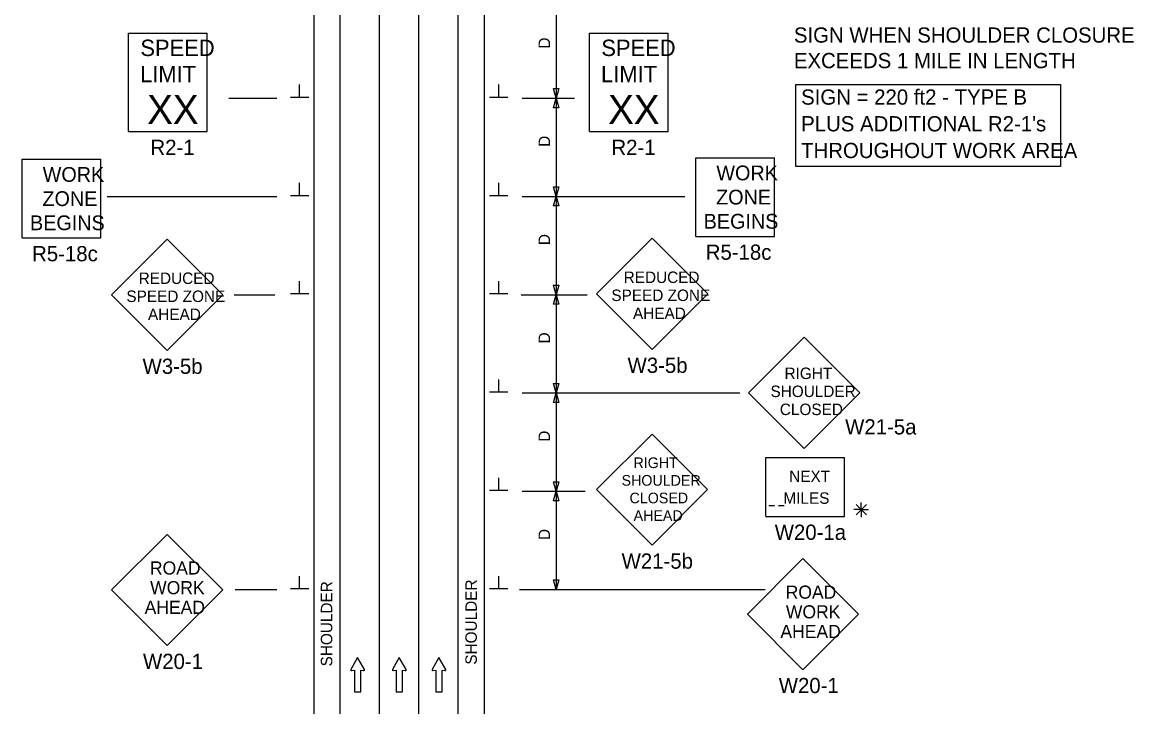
# Model space of a CAD drawing. Extents: x 16733 to 18471, y 7027 to 8225.
# Drawn here: x 16768 to 17446, y 7435 to 7852 of the extents above; entities that cross this region are included whole.
import ezdxf

# ---------------------------------------------------------------- set-up
doc = ezdxf.new("R2010")
doc.units = 0
for name, color, linetype in [('ALI_LEGAL_EX', 7, 'Continuous'), ('MT_SCRATCH_LEVEL_E', 7, 'Continuous'), ('PAVT_EDGE_EX', 7, 'Continuous'), ('TRAFFIC_SIGNS_PR', 7, 'Continuous'), ('TYPICAL_TEXT_DIMEN_EX', 7, 'Continuous'), ('TYPICAL_TEXT_DIMEN_PR', 7, 'Continuous')]:
    doc.layers.add(name, color=color, linetype=linetype)

msp = doc.modelspace()

# ---------------------------------------------------------------- linework, layer by layer
at = {"layer": 'ALI_LEGAL_EX'}
for points in [[(16985.65, 7825.29), (16985.65, 7800.29)], [(17009.65, 7825.29), (17009.65, 7800.29)], [(16985.65, 7725.29), (16985.65, 7700.29)], [(17009.65, 7725.29), (17009.65, 7700.29)], [(16985.65, 7625.29), (16985.65, 7600.29)], [(17009.65, 7625.29), (17009.65, 7600.29)], [(16985.65, 7525.29), (16985.65, 7500.29)], [(17009.65, 7525.29), (17009.65, 7500.29)]]:
    msp.add_lwpolyline(points, dxfattribs=at)
at = {"layer": 'MT_SCRATCH_LEVEL_E'}
for p, q in [((16972.46, 7464.59), (16968.34, 7457.35)), ((16972.46, 7464.59), (16968.34, 7457.35)), ((16976.6, 7457.35), (16972.46, 7464.59)), ((16976.6, 7457.35), (16972.46, 7464.59)), ((16997.88, 7464.59), (16993.77, 7457.35)), ((16997.88, 7464.59), (16993.77, 7457.35)), ((17002.03, 7457.35), (16997.88, 7464.59)), ((17002.03, 7457.35), (16997.88, 7464.59)), ((17022.09, 7464.59), (17017.98, 7457.35)), ((17022.09, 7464.59), (17017.98, 7457.35)), ((17026.24, 7457.35), (17022.09, 7464.59)), ((17026.24, 7457.35), (17022.09, 7464.59)), ((16968.83, 7456.67), (16970.6, 7456.99)), ((16968.83, 7456.67), (16970.6, 7456.99)), ((16970.6, 7456.99), (16970.6, 7443.73)), ((16970.6, 7456.99), (16970.6, 7443.73)), ((16974.35, 7443.73), (16974.35, 7456.99)), ((16974.35, 7456.99), (16976.12, 7456.67)), ((16974.35, 7443.73), (16974.35, 7456.99)), ((16974.35, 7456.99), (16976.12, 7456.67)), ((16994.25, 7456.67), (16996.03, 7456.99)), ((16994.25, 7456.67), (16996.03, 7456.99)), ((16996.03, 7456.99), (16996.03, 7443.73)), ((16996.03, 7456.99), (16996.03, 7443.73)), ((16999.77, 7443.73), (16999.77, 7456.99)), ((16999.77, 7456.99), (17001.55, 7456.67)), ((16999.77, 7443.73), (16999.77, 7456.99)), ((16999.77, 7456.99), (17001.55, 7456.67)), ((17018.47, 7456.67), (17020.24, 7456.99)), ((17018.47, 7456.67), (17020.24, 7456.99)), ((17020.24, 7456.99), (17020.24, 7443.73)), ((17020.24, 7456.99), (17020.24, 7443.73)), ((17023.98, 7443.73), (17023.98, 7456.99)), ((17023.98, 7456.99), (17025.76, 7456.67)), ((17023.98, 7443.73), (17023.98, 7456.99)), ((17023.98, 7456.99), (17025.76, 7456.67)), ((16970.6, 7443.73), (16974.35, 7443.73)), ((16970.6, 7443.73), (16974.35, 7443.73)), ((16996.03, 7443.73), (16999.77, 7443.73)), ((16996.03, 7443.73), (16999.77, 7443.73)), ((17020.24, 7443.73), (17023.98, 7443.73)), ((17020.24, 7443.73), (17023.98, 7443.73))]:
    msp.add_line(p, q, dxfattribs=at)
for centre, start, end in [((16968.75, 7457.13), 150.42484, 279.96381), ((16968.75, 7457.13), 150.42484, 279.96381), ((16976.19, 7457.13), 260.03619, 29.77312), ((16976.19, 7457.13), 260.03619, 29.77312), ((16994.18, 7457.13), 150.42484, 279.96381), ((16994.18, 7457.13), 150.42484, 279.96381), ((17001.62, 7457.13), 260.03619, 29.77312), ((17001.62, 7457.13), 260.03619, 29.77312), ((17018.39, 7457.13), 150.42484, 279.96381), ((17018.39, 7457.13), 150.42484, 279.96381), ((17025.83, 7457.13), 260.03619, 29.77312), ((17025.83, 7457.13), 260.03619, 29.77312)]:
    msp.add_arc(centre, 0.463, start, end, dxfattribs=at)
at = {"layer": 'PAVT_EDGE_EX'}
for p, q in [((16985.65, 8211.96), (16985.65, 7344.79)), ((17009.65, 8211.96), (17009.65, 7344.79)), ((16985.65, 8097.28), (16985.65, 7344.79)), ((17009.65, 8097.28), (17009.65, 7344.79)), ((16945.65, 7942.5), (16945.65, 7379.34)), ((16961.65, 7942.41), (16961.65, 7379.34)), ((17033.65, 7942.16), (17033.65, 7379.34)), ((17049.65, 7942.41), (17049.65, 7379.34))]:
    msp.add_line(p, q, dxfattribs=at)
at = {"layer": 'TRAFFIC_SIGNS_PR'}
for p, q in [((16832.67, 7845.71), (16880.67, 7845.71)), ((16832.67, 7785.71), (16832.67, 7845.71)), ((16880.67, 7785.71), (16880.67, 7845.71)), ((17114.03, 7845.71), (17162.03, 7845.71)), ((17114.03, 7785.71), (17114.03, 7845.71)), ((17162.03, 7785.71), (17162.03, 7845.71)), ((16832.67, 7785.71), (16880.67, 7785.71)), ((17114.03, 7785.71), (17162.03, 7785.71)), ((16767.76, 7720.8), (16767.76, 7768.8)), ((16767.76, 7768.8), (16815.76, 7768.8)), ((16815.76, 7720.8), (16815.76, 7768.8)), ((17178.94, 7721.73), (17178.94, 7769.73)), ((17178.94, 7769.73), (17226.94, 7769.73)), ((17226.94, 7721.73), (17226.94, 7769.73)), ((16767.76, 7720.8), (16815.76, 7720.8)), ((17178.94, 7721.73), (17226.94, 7721.73)), ((16856.27, 7719.97), (16822.33, 7686.03)), ((16890.21, 7686.03), (16856.27, 7719.97)), ((17152.28, 7720.57), (17118.34, 7686.63)), ((17186.22, 7686.63), (17152.28, 7720.57)), ((16822.33, 7686.03), (16856.27, 7652.08)), ((16856.27, 7652.08), (16890.21, 7686.03)), ((17118.34, 7686.63), (17152.28, 7652.69)), ((17152.28, 7652.69), (17186.22, 7686.63)), ((17244.98, 7660.13), (17211.04, 7626.19)), ((17278.92, 7626.19), (17244.98, 7660.13)), ((17211.04, 7626.19), (17244.98, 7592.25)), ((17244.98, 7592.25), (17278.92, 7626.19)), ((17152.16, 7601.07), (17118.22, 7567.13)), ((17186.11, 7567.13), (17152.16, 7601.07)), ((17221.63, 7550.78), (17221.63, 7586.78)), ((17221.63, 7586.78), (17269.63, 7586.78)), ((17269.63, 7550.78), (17269.63, 7586.78)), ((17118.22, 7567.13), (17152.16, 7533.19)), ((17152.16, 7533.19), (17186.11, 7567.13)), ((17223.49, 7557.38), (17226.99, 7557.38)), ((17229.29, 7557.38), (17232.79, 7557.38)), ((17221.63, 7550.78), (17269.63, 7550.78)), ((16856.26, 7539.84), (16822.32, 7505.9)), ((16890.2, 7505.9), (16856.26, 7539.84)), ((17244.3, 7525.1), (17210.36, 7491.16)), ((17278.25, 7491.16), (17244.3, 7525.1)), ((16822.32, 7505.9), (16856.26, 7471.96)), ((16856.26, 7471.96), (16890.2, 7505.9)), ((17210.36, 7491.16), (17244.3, 7457.22)), ((17244.3, 7457.22), (17278.25, 7491.16))]:
    msp.add_line(p, q, dxfattribs=at)
at = {"layer": 'TYPICAL_TEXT_DIMEN_EX'}
msp.add_lwpolyline([(17240.03, 7814.52), (17401.44, 7814.52), (17401.44, 7764.45), (17240.03, 7764.45)], close=True, dxfattribs=at)
at = {"layer": 'TYPICAL_TEXT_DIMEN_PR'}
for p, q in [((17093.65, 7866.13), (17093.65, 7806.13)), ((16937.02, 7806.56), (16937.02, 7814.34)), ((17058.58, 7806.56), (17058.58, 7814.34)), ((17093.65, 7806.13), (17092.08, 7811.99)), ((17092.08, 7811.99), (17093.65, 7811.99)), ((17093.65, 7811.99), (17095.22, 7811.99)), ((17095.22, 7811.99), (17093.65, 7806.13)), ((16893.76, 7806.13), (16923.12, 7806.13)), ((16942.65, 7806.56), (16931.4, 7806.56)), ((17064.21, 7806.56), (17052.96, 7806.56)), ((17072.81, 7806.13), (17104.89, 7806.13)), ((17092.08, 7800.27), (17093.65, 7806.13)), ((17093.65, 7806.13), (17093.65, 7746.13)), ((17093.65, 7806.13), (17095.22, 7800.27)), ((17093.65, 7800.27), (17092.08, 7800.27)), ((17095.22, 7800.27), (17093.65, 7800.27)), ((16937.02, 7746.56), (16937.02, 7754.34)), ((17058.58, 7746.56), (17058.58, 7754.34)), ((17093.65, 7746.13), (17092.08, 7751.99)), ((17092.08, 7751.99), (17093.65, 7751.99)), ((17093.65, 7751.99), (17095.22, 7751.99)), ((17095.22, 7751.99), (17093.65, 7746.13)), ((16819.52, 7746.13), (16923.12, 7746.13)), ((16942.65, 7746.56), (16931.4, 7746.56)), ((17064.21, 7746.56), (17052.96, 7746.56)), ((17072.81, 7746.13), (17172.09, 7746.13)), ((17092.08, 7740.27), (17093.65, 7746.13)), ((17093.65, 7746.13), (17093.65, 7686.13)), ((17093.65, 7746.13), (17095.22, 7740.27)), ((17093.65, 7740.27), (17092.08, 7740.27)), ((17095.22, 7740.27), (17093.65, 7740.27)), ((16937.02, 7686.56), (16937.02, 7694.34)), ((17058.58, 7686.56), (17058.58, 7694.34)), ((17093.65, 7686.13), (17092.08, 7691.99)), ((17092.08, 7691.99), (17093.65, 7691.99)), ((17093.65, 7691.99), (17095.22, 7691.99)), ((17095.22, 7691.99), (17093.65, 7686.13)), ((16897.21, 7686.13), (16921.99, 7686.13)), ((16942.65, 7686.56), (16931.4, 7686.56)), ((17064.21, 7686.56), (17052.96, 7686.56)), ((17072.33, 7686.13), (17112.53, 7686.13)), ((17092.08, 7680.27), (17093.65, 7686.13)), ((17093.65, 7680.27), (17092.08, 7680.27)), ((17093.65, 7686.13), (17093.65, 7626.13)), ((17093.65, 7686.13), (17095.22, 7680.27)), ((17095.22, 7680.27), (17093.65, 7680.27)), ((17058.58, 7626.56), (17058.58, 7634.34)), ((17064.21, 7626.56), (17052.96, 7626.56)), ((17072.81, 7626.13), (17205.68, 7626.13)), ((17093.65, 7626.13), (17092.08, 7631.99)), ((17092.08, 7631.99), (17093.65, 7631.99)), ((17092.08, 7620.27), (17093.65, 7626.13)), ((17093.65, 7631.99), (17095.22, 7631.99)), ((17095.22, 7631.99), (17093.65, 7626.13)), ((17093.65, 7626.13), (17093.65, 7566.13)), ((17093.65, 7626.13), (17095.22, 7620.27)), ((17093.65, 7620.27), (17092.08, 7620.27)), ((17095.22, 7620.27), (17093.65, 7620.27)), ((17058.58, 7566.56), (17058.58, 7574.34)), ((17093.65, 7566.13), (17092.08, 7571.99)), ((17092.08, 7571.99), (17093.65, 7571.99)), ((17093.65, 7571.99), (17095.22, 7571.99)), ((17095.22, 7571.99), (17093.65, 7566.13)), ((17064.21, 7566.56), (17052.96, 7566.56)), ((17072.81, 7566.13), (17111.32, 7566.13)), ((17092.08, 7560.27), (17093.65, 7566.13)), ((17093.65, 7566.13), (17093.65, 7506.13)), ((17093.65, 7566.13), (17095.22, 7560.27)), ((17093.65, 7560.27), (17092.08, 7560.27)), ((17095.22, 7560.27), (17093.65, 7560.27)), ((17276.73, 7558.11), (17283.1, 7551.74)), ((17283.1, 7558.11), (17276.73, 7551.74)), ((17279.91, 7554.92), (17279.91, 7559.38)), ((17279.91, 7554.92), (17275.38, 7554.92)), ((17279.91, 7554.92), (17283.1, 7554.92)), ((17279.91, 7554.92), (17284.39, 7554.92)), ((17279.91, 7554.92), (17279.91, 7550.42)), ((16937.02, 7506.56), (16937.02, 7514.34)), ((17058.58, 7506.56), (17058.58, 7514.34)), ((17093.65, 7506.13), (17092.08, 7511.99)), ((17092.08, 7511.99), (17093.65, 7511.99)), ((17093.65, 7511.99), (17095.22, 7511.99)), ((17095.22, 7511.99), (17093.65, 7506.13)), ((16897.81, 7506.13), (16923.12, 7506.13)), ((16942.65, 7506.56), (16931.4, 7506.56)), ((17064.21, 7506.56), (17052.96, 7506.56)), ((17071.2, 7506.13), (17221.12, 7506.13))]:
    msp.add_line(p, q, dxfattribs=at)

# ---------------------------------------------------------------- texts
at = {"layer": 'TRAFFIC_SIGNS_PR'}
for s, height, p in [('SPEED', 10, (16839.88, 7831.79)), ('SPEED', 10, (17121.24, 7831.79)), ('LIMIT', 10, (16839.67, 7815.79)), ('LIMIT', 10, (17121.04, 7815.79)), ('XX', 17.538, (16844.06, 7790.41)), ('XX', 17.538, (17125.42, 7790.41)), ('R2-1', 9.3, (16846.01, 7771.41)), ('R2-1', 9.3, (17127.38, 7771.41)), ('WORK', 9.021, (16780.26, 7755.01)), ('WORK', 9.021, (17191.44, 7755.94)), ('ZONE', 9.021, (16780.11, 7740.25)), ('ZONE', 9.021, (17191.29, 7741.18)), ('BEGINS', 9.021, (16772.52, 7725.49)), ('BEGINS', 9.021, (17183.7, 7726.42)), ('R5-18c', 9.3, (16773.78, 7706.51)), ('R5-18c', 9.3, (17184.95, 7707.43)), ('REDUCED', 7, (17134.86, 7693.26)), ('REDUCED', 7, (16838.84, 7692.66)), ('SPEED ZONE', 7, (16831.33, 7681.66)), ('SPEED ZONE', 7, (17127.35, 7682.26)), ('AHEAD', 7, (16844.53, 7670.66)), ('AHEAD', 7, (17140.55, 7671.26)), ('W3-5b', 9.3, (16841.21, 7637.78)), ('W3-5b', 9.3, (17137.23, 7638.39)), ('RIGHT', 7, (17233.03, 7634.64)), ('SHOULDER', 7, (17224.46, 7623.64)), ('CLOSED', 7, (17230.17, 7612.64)), ('W21-5a', 9.3, (17270.04, 7600.81)), ('RIGHT', 6.5, (17140.84, 7580.3)), ('NEXT', 7, (17235.89, 7571.78)), ('SHOULDER', 6.5, (17133.57, 7569.55)), ('CLOSED', 6.5, (17138.46, 7558.8)), ('   MILES', 7, (17224.55, 7558.48)), ('AHEAD', 6.5, (17140.91, 7548.05)), ('W20-1a', 9.3, (17227.06, 7536.48)), ('W21-5b', 9.3, (17133.61, 7518.89)), ('ROAD', 8, (16845.69, 7515.32)), ('WORK', 8, (16845.82, 7503.32)), ('ROAD', 8, (17233.73, 7500.58)), ('AHEAD', 8, (16842.46, 7491.32)), ('WORK', 8, (17233.87, 7488.58)), ('AHEAD', 8, (17230.51, 7476.58)), ('W20-1', 9.3, (16841.47, 7457.66)), ('W20-1', 9.3, (17229.52, 7442.92))]:
    msp.add_text(s, height=height, dxfattribs=at).set_placement(p)
at = {"layer": 'TYPICAL_TEXT_DIMEN_EX'}
for s, p in [('SIGN WHEN SHOULDER CLOSURE', (17238.75, 7839.97)), ('EXCEEDS 1 MILE IN LENGTH', (17238.75, 7824.37)), ('SIGN = 220 ft2 - TYPE B', (17243.17, 7802.11)), ("PLUS ADDITIONAL R2-1's", (17243.17, 7785.81)), ('THROUGHOUT WORK AREA', (17243.17, 7769.51))]:
    msp.add_text(s, height=9.3, dxfattribs=at).set_placement(p)
at = {"layer": 'TYPICAL_TEXT_DIMEN_PR'}
for s, p in [('D', (17089.92, 7836.37)), ('D', (17089.92, 7776.37)), ('D', (17089.92, 7716.37)), ('D', (17089.92, 7656.37)), ('D', (17089.92, 7596.37)), ('D', (17089.92, 7536.37)), ('SHOULDER', (16957.01, 7459.24)), ('SHOULDER', (17045.24, 7460.3))]:
    msp.add_text(s, height=7, rotation=90, dxfattribs=at).set_placement(p)

doc.saveas('drawing.dxf')
